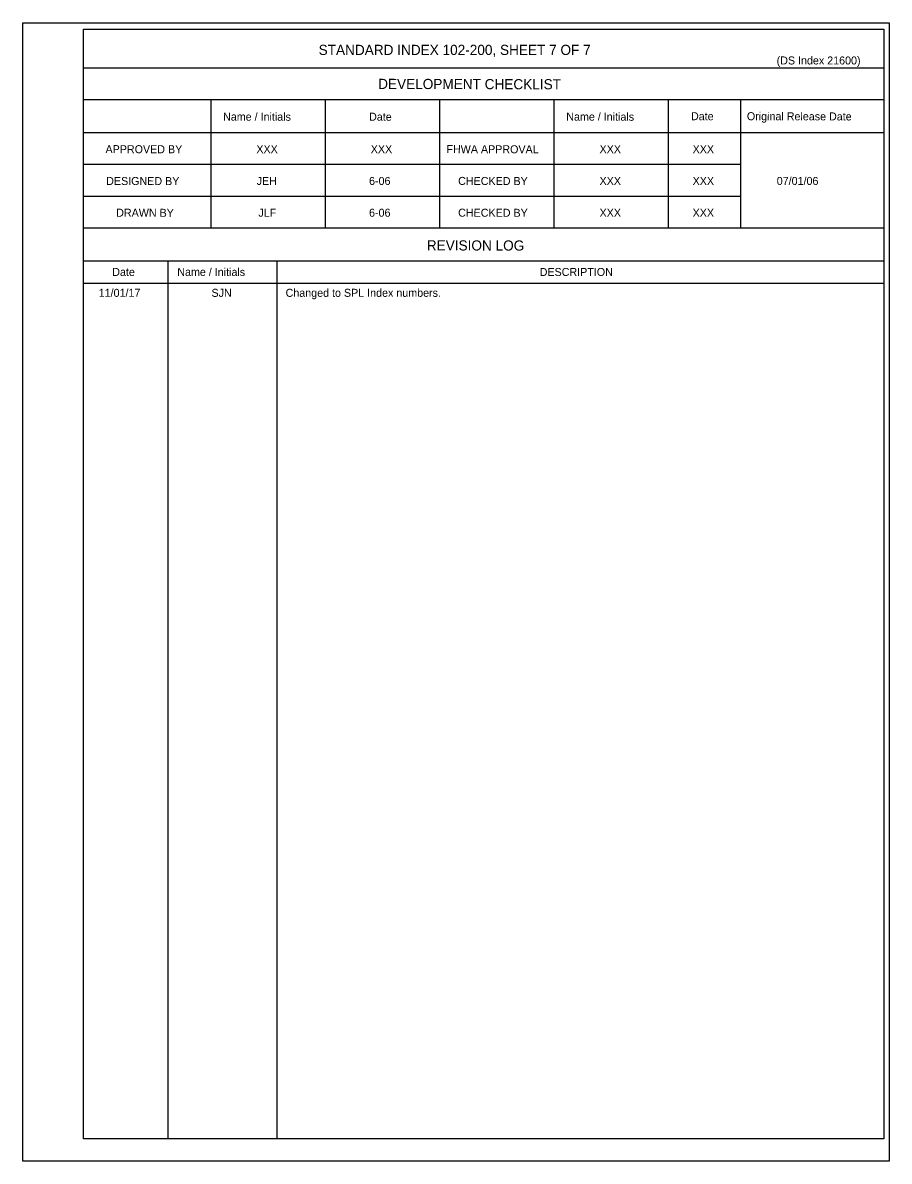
# Model space of a CAD drawing. Extents: x 10625 to 10695.9, y 76470.9 to 76509.2.
# Drawn here: x 10674.13 to 10695.94, y 76477.23 to 76505.89 of the extents above; entities that cross this region are included whole.
import ezdxf

# ---------------------------------------------------------------- set-up
doc = ezdxf.new("R2010")
doc.units = 0
for name, color, linetype in [('Border', 7, 'Continuous'), ('PlotBorder_dp', 7, 'Continuous'), ('TextStructures', 7, 'Continuous')]:
    doc.layers.add(name, color=color, linetype=linetype)

msp = doc.modelspace()

# ---------------------------------------------------------------- linework, layer by layer
at = {"layer": 'Border'}
for p, q in [((10695.807, 76504.749), (10675.66, 76504.749)), ((10695.807, 76503.949), (10675.66, 76503.949)), ((10678.86, 76503.949), (10678.86, 76500.721)), ((10681.74, 76503.949), (10681.74, 76500.721)), ((10684.62, 76503.949), (10684.62, 76500.721)), ((10687.5, 76503.949), (10687.5, 76500.721)), ((10690.38, 76503.949), (10690.38, 76500.721)), ((10692.195, 76503.949), (10692.195, 76500.721)), ((10695.807, 76503.121), (10675.66, 76503.121)), ((10692.195, 76502.321), (10675.66, 76502.321)), ((10692.195, 76501.521), (10675.66, 76501.521)), ((10695.807, 76500.721), (10675.66, 76500.721)), ((10695.807, 76499.893), (10675.66, 76499.893)), ((10677.78, 76499.893), (10677.78, 76477.787)), ((10680.523, 76499.893), (10680.523, 76477.787)), ((10695.807, 76499.329), (10675.66, 76499.329))]:
    msp.add_line(p, q, dxfattribs=at)
msp.add_lwpolyline([(10675.66, 76505.729), (10695.807, 76505.729), (10695.807, 76477.787), (10675.66, 76477.787)], close=True, dxfattribs=at)
at = {"layer": 'PlotBorder_dp'}
msp.add_line((10674.129, 76477.225), (10674.129, 76477.225), dxfattribs=at)
msp.add_lwpolyline([(10674.129, 76505.892), (10695.943, 76505.892), (10695.943, 76477.225), (10674.129, 76477.225)], close=True, dxfattribs=at)

# ---------------------------------------------------------------- texts
at = {"layer": 'TextStructures'}
for s, height, p in [('STANDARD INDEX 102-200, SHEET 7 OF 7', 0.256, (10681.578, 76505.081)), ('(DS Index 21600)', 0.2016, (10693.108, 76504.842)), ('XXX', 0.2016, (10680.01, 76502.608)), ('XXX', 0.2016, (10682.89, 76502.608)), ('XXX', 0.2016, (10688.65, 76502.608)), ('XXX', 0.2016, (10690.993, 76502.608)), ('JEH', 0.2016, (10680.017, 76501.808)), ('6-06', 0.2016, (10682.847, 76501.808)), ('XXX', 0.2016, (10688.65, 76501.808)), ('XXX', 0.2016, (10690.993, 76501.808)), ('07/01/06', 0.2016, (10693.111, 76501.808)), ('JLF', 0.2016, (10680.06, 76501.008)), ('6-06', 0.2016, (10682.847, 76501.008)), ('XXX', 0.2016, (10688.65, 76501.008)), ('XXX', 0.2016, (10690.993, 76501.008)), ('DESCRIPTION', 0.2016, (10687.143, 76499.516)), ('11/01/17', 0.2016, (10676.041, 76498.991)), ('SJN', 0.2016, (10678.881, 76498.991)), ('Changed to SPL Index numbers.', 0.2016, (10680.746, 76498.991))]:
    msp.add_text(s, height=height, dxfattribs=at).set_placement(p)
for s, height, p in [('DEVELOPMENT CHECKLIST', 0.256, (10683.076, 76504.225)), ('Name / Initials', 0.2016, (10679.172, 76503.428)), ('Date', 0.2016, (10682.847, 76503.426)), ('Name / Initials', 0.2016, (10687.812, 76503.428)), ('Date', 0.2016, (10690.952, 76503.438)), ('Original Release Date', 0.2016, (10692.359, 76503.438)), ('APPROVED BY', 0.2016, (10676.212, 76502.609)), ('FHWA APPROVAL', 0.2016, (10684.795, 76502.609)), ('DESIGNED BY', 0.2016, (10676.229, 76501.808)), ('CHECKED BY', 0.2016, (10685.09, 76501.809)), ('DRAWN BY', 0.2016, (10676.481, 76501.008)), ('CHECKED BY', 0.2016, (10685.09, 76501.009)), ('REVISION LOG', 0.256, (10684.301, 76500.16)), ('Date', 0.2016, (10676.382, 76499.517)), ('Name / Initials', 0.2016, (10678.019, 76499.518))]:
    msp.add_text(s, height=height, rotation=359.8756, dxfattribs=at).set_placement(p)

doc.saveas('drawing.dxf')
